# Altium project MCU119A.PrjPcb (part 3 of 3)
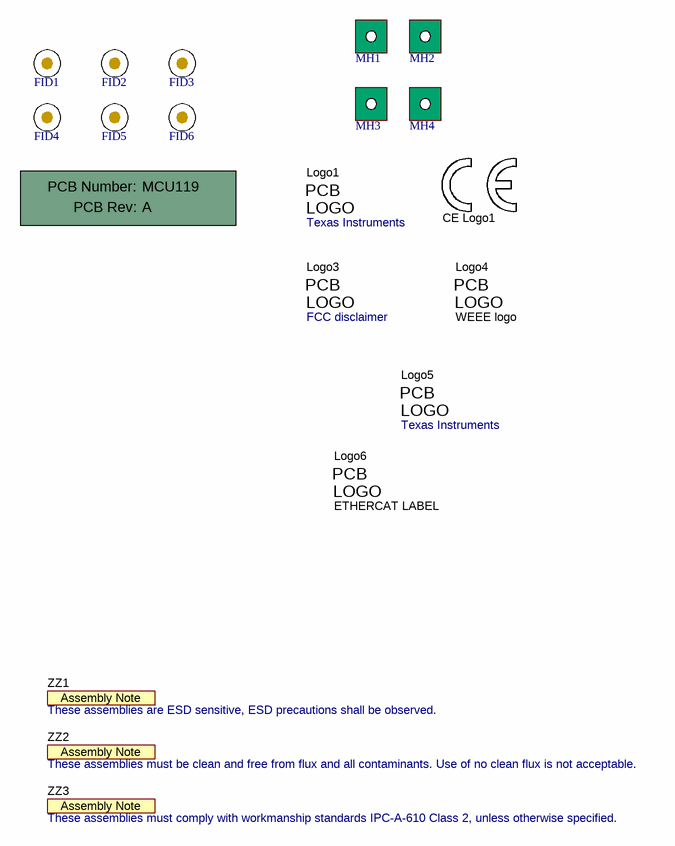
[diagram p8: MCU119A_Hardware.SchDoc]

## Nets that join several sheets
+1V25_MCU: MCU119A_F29H85X_Device (C59.1 L1.1), MCU119A_USB_and_Power (C85.1 L5.2 R72.2 TP11.1)
+3V3_MCU: MCU119A_Connectors (5 pins), MCU119A_F29H85X_Device (6 pins), MCU119A_USB_and_Power (14 pins), MCU119A_XDS110_MCU (R74.2 R76.2), MCU119A_AltRouting_Misc (24 pins)
+3V3_XDS110: MCU119A_USB_and_Power (C126.1 R96.1 U25.5), MCU119A_XDS110_MCU (37 pins)
+5V0_MCU: MCU119A_Connectors (14 pins), MCU119A_USB_and_Power (20 pins), MCU119A_AltRouting_Misc (C22.1 C23.1 U13.23 U13.24)
+5V0_USB: MCU119A_USB_and_Power (12 pins), MCU119A_XDS110_MCU (R164.1)
GND: MCU119A_Connectors (25 pins), MCU119A_F29H85X_Device (38 pins), MCU119A_ADC (34 pins), MCU119A_USB_and_Power (39 pins), MCU119A_XDS110_MCU (13 pins), MCU119A_AltRouting_Misc (36 pins)
USB_GND: MCU119A_USB_and_Power (22 pins), MCU119A_XDS110_MCU (36 pins)
VDD: MCU119A_F29H85X_Device (20 pins), MCU119A_USB_and_Power (C74.2 C75.2 JP4.1 TP1.1)
VDDA: MCU119A_F29H85X_Device (5 pins), MCU119A_ADC (C51.1 C53.1 U3.2 U12.8), MCU119A_USB_and_Power (TP3.1)
VDDIO: MCU119A_F29H85X_Device (30 pins), MCU119A_USB_and_Power (TP2.1)
ADCINA0/DACA_OUT: MCU119A_Connectors (J1/J3.30), MCU119A_ADC (R37.1)
ADCINA1: MCU119A_Connectors (J1/J3.2), MCU119A_ADC (R38.1)
ADCINA2: MCU119A_Connectors (J1/J3.6), MCU119A_ADC (R39.1)
ADCINA3: MCU119A_Connectors (J1/J3.24), MCU119A_ADC (R40.1)
ADCINA4A5_N: MCU119A_Connectors (J10.3), MCU119A_ADC (R42.1)
ADCINA4A5_P: MCU119A_Connectors (J10.1), MCU119A_ADC (R41.1)
ADCINA6: MCU119A_Connectors (J5/J7.64), MCU119A_ADC (R43.1)
ADCINA7: MCU119A_Connectors (J1/J3.28), MCU119A_ADC (R45.1)
ADCINA14/B14/C14/D14/E14: MCU119A_Connectors (J1/J3.23), MCU119A_ADC (R46.1)
ADCINA15/B15/C15/D15/E15: MCU119A_Connectors (J5/J7.63), MCU119A_ADC (R47.1)
ADCINB2B3_N: MCU119A_Connectors (J10.4), MCU119A_ADC (R49.1)
ADCINB2B3_P: MCU119A_Connectors (J10.2), MCU119A_ADC (R48.1)
ADCINB4: MCU119A_Connectors (J1/J3.27), MCU119A_ADC (R50.1)
ADCINB9: MCU119A_Connectors (J5/J7.67), MCU119A_ADC (R51.1)
ADCINC0: MCU119A_Connectors (J5/J7.68), MCU119A_ADC (R52.1)
ADCINC1: MCU119A_Connectors (J1/J3.29), MCU119A_ADC (R53.1)
ADCINC2: MCU119A_Connectors (J5/J7.42), MCU119A_ADC (R54.1)
ADCINC3: MCU119A_Connectors (J5/J7.46), MCU119A_ADC (R55.1)
ADCINC8: MCU119A_Connectors (J5/J7.66), MCU119A_ADC (R56.1)
ADCIND1: MCU119A_Connectors (J1/J3.25), MCU119A_ADC (R57.1)
ADCIND5: MCU119A_Connectors (J5/J7.65), MCU119A_ADC (R58.1)
ADCINE0/DACB_OUT: MCU119A_Connectors (J5/J7.70), MCU119A_ADC (R60.1)
ADCINE1: MCU119A_Connectors (J5/J7.69), MCU119A_ADC (R61.1)
ADCINE7: MCU119A_Connectors (J1/J3.26), MCU119A_ADC (R62.1)
EQEP1A: MCU119A_Connectors (C6.1 J12.1 R5.1), MCU119A_AltRouting_Misc (U13.21)
EQEP1B: MCU119A_Connectors (C7.1 J12.2 R6.1), MCU119A_AltRouting_Misc (U13.20)
EQEP1I: MCU119A_Connectors (C8.1 J12.3 R7.1), MCU119A_AltRouting_Misc (U13.19)
EQEP2A: MCU119A_Connectors (C9.1 J13.1 R8.1), MCU119A_AltRouting_Misc (U13.18)
EQEP2B: MCU119A_Connectors (C10.1 J13.2 R9.1), MCU119A_AltRouting_Misc (U13.17)
EQEP2I: MCU119A_Connectors (C11.1 J13.3 R10.1), MCU119A_AltRouting_Misc (U13.16)
ERRORSTS: MCU119A_F29H85X_Device (U1.74), MCU119A_USB_and_Power (R26.2 R27.2)
GPIO0: MCU119A_Connectors (R1.2), MCU119A_F29H85X_Device (U1.128)
GPIO1: MCU119A_Connectors (R2.2), MCU119A_F29H85X_Device (U1.129)
GPIO2: MCU119A_Connectors (J4/J2.38), MCU119A_F29H85X_Device (U1.130)
GPIO3: MCU119A_Connectors (J4/J2.37), MCU119A_F29H85X_Device (U1.131)
GPIO4: MCU119A_Connectors (J4/J2.36), MCU119A_F29H85X_Device (U1.132)
GPIO5: MCU119A_Connectors (J4/J2.35), MCU119A_F29H85X_Device (U1.133)
GPIO6: MCU119A_Connectors (R3.2), MCU119A_F29H85X_Device (U1.134)
GPIO7: MCU119A_Connectors (R4.2), MCU119A_F29H85X_Device (U1.135)
GPIO8: MCU119A_Connectors (J8/J6.78), MCU119A_F29H85X_Device (U1.138)
GPIO9: MCU119A_Connectors (J8/J6.77), MCU119A_F29H85X_Device (U1.139)
GPIO10: MCU119A_F29H85X_Device (U1.140), MCU119A_AltRouting_Misc (U11.15)
GPIO10_BP: MCU119A_Connectors (J8/J6.57), MCU119A_AltRouting_Misc (U11.1)
GPIO11: MCU119A_F29H85X_Device (U1.141), MCU119A_AltRouting_Misc (U11.14)
GPIO11_BP: MCU119A_Connectors (J8/J6.58), MCU119A_AltRouting_Misc (U11.13)
GPIO12: MCU119A_Connectors (J8/J6.76), MCU119A_F29H85X_Device (U1.142)
GPIO13: MCU119A_Connectors (J8/J6.75), MCU119A_F29H85X_Device (U1.143)
GPIO14: MCU119A_Connectors (J4/J2.34), MCU119A_F29H85X_Device (U1.144)
GPIO15: MCU119A_Connectors (J4/J2.33), MCU119A_F29H85X_Device (U1.1)
GPIO17: MCU119A_F29H85X_Device (U1.4), MCU119A_AltRouting_Misc (U14.15)
GPIO17_BP: MCU119A_Connectors (J4/J2.17), MCU119A_AltRouting_Misc (U14.1)
GPIO18: MCU119A_Connectors (J4/J2.11), MCU119A_F29H85X_Device (U1.10)
GPIO19: MCU119A_Connectors (J4/J2.13), MCU119A_F29H85X_Device (U1.5), MCU119A_AltRouting_Misc (R17.1)
GPIO22: MCU119A_Connectors (J5/J7.50), MCU119A_F29H85X_Device (U1.11), MCU119A_USB_and_Power (R32.1)
GPIO23: MCU119A_Connectors (J15.5 R24.2), MCU119A_F29H85X_Device (U1.127)
GPIO24: MCU119A_Connectors (J8/J6.74), MCU119A_F29H85X_Device (U1.126)
GPIO25: MCU119A_Connectors (J8/J6.54), MCU119A_F29H85X_Device (U1.125)
GPIO26: MCU119A_Connectors (J5/J7.47), MCU119A_F29H85X_Device (U1.124)
GPIO29: MCU119A_Connectors (J15.2 R23.1), MCU119A_F29H85X_Device (U1.121)
GPIO30: MCU119A_F29H85X_Device (U1.120), MCU119A_USB_and_Power (U10.21)
GPIO32: MCU119A_F29H85X_Device (U1.96), MCU119A_AltRouting_Misc (U11.4)
GPIO32_BP: MCU119A_Connectors (J8/J6.52), MCU119A_AltRouting_Misc (U11.3)
GPIO34: MCU119A_F29H85X_Device (U1.7), MCU119A_AltRouting_Misc (U14.4)
GPIO34_BP: MCU119A_Connectors (J4/J2.12), MCU119A_AltRouting_Misc (U14.3)
GPIO38: MCU119A_Connectors (J5/J7.45), MCU119A_F29H85X_Device (U1.104)
GPIO41: MCU119A_Connectors (J5/J7.49), MCU119A_F29H85X_Device (U1.73), MCU119A_USB_and_Power (R29.1)
GPIO42: MCU119A_F29H85X_Device (U1.107), MCU119A_AltRouting_Misc (U6.6)
GPIO42_BP: MCU119A_Connectors (J1/J3.4), MCU119A_AltRouting_Misc (U6.4)
GPIO43: MCU119A_F29H85X_Device (U1.108), MCU119A_AltRouting_Misc (U6.10)
GPIO43_BP: MCU119A_Connectors (J1/J3.3), MCU119A_AltRouting_Misc (U6.2)
GPIO49_FSITXD0: MCU119A_Connectors (J11.6), MCU119A_F29H85X_Device (U1.75)
GPIO50_FSITXD1: MCU119A_Connectors (J11.8), MCU119A_F29H85X_Device (U1.76)
GPIO51_FSITXCLK: MCU119A_Connectors (J11.2), MCU119A_F29H85X_Device (U1.77)
GPIO52_FSIRXD0: MCU119A_Connectors (J11.5), MCU119A_F29H85X_Device (U1.78)
GPIO53_FSIRXD1: MCU119A_Connectors (J11.7), MCU119A_F29H85X_Device (U1.79)
GPIO54_FSIRXCLK: MCU119A_Connectors (J11.1), MCU119A_F29H85X_Device (U1.80)
GPIO56: MCU119A_Connectors (J1/J3.10), MCU119A_F29H85X_Device (U1.82)
GPIO57: MCU119A_Connectors (J1/J3.9), MCU119A_F29H85X_Device (U1.84)
GPIO58: MCU119A_Connectors (J4/J2.15), MCU119A_F29H85X_Device (U1.85)
GPIO59: MCU119A_Connectors (J4/J2.14), MCU119A_F29H85X_Device (U1.86)
GPIO60: MCU119A_Connectors (J1/J3.7), MCU119A_F29H85X_Device (U1.88)
GPIO61: MCU119A_Connectors (J4/J2.19), MCU119A_F29H85X_Device (U1.89)
GPIO62: MCU119A_Connectors (J8/J6.53), MCU119A_F29H85X_Device (U1.90), MCU119A_AltRouting_Misc (R19.1)
GPIO63: MCU119A_Connectors (J8/J6.55), MCU119A_F29H85X_Device (U1.91)
GPIO64: MCU119A_F29H85X_Device (U1.92), MCU119A_AltRouting_Misc (S4.2)
GPIO64_BP: MCU119A_Connectors (J4/J2.32), MCU119A_AltRouting_Misc (S4.3)
GPIO64_CANTX: MCU119A_Connectors (TP7.1 U15.1), MCU119A_AltRouting_Misc (S4.1)
GPIO65: MCU119A_F29H85X_Device (U1.93), MCU119A_AltRouting_Misc (S4.5)
GPIO65_BP: MCU119A_Connectors (J4/J2.31), MCU119A_AltRouting_Misc (S4.6)
GPIO65_CANRX: MCU119A_Connectors (TP8.1 U15.4), MCU119A_AltRouting_Misc (S4.4)
GPIO66: MCU119A_Connectors (J8/J6.59), MCU119A_F29H85X_Device (U1.94)
GPIO68: MCU119A_Connectors (J8/J6.73), MCU119A_F29H85X_Device (U1.109)
GPIO70: MCU119A_F29H85X_Device (U1.110), MCU119A_AltRouting_Misc (U8.10)
GPIO70_BP: MCU119A_Connectors (J5/J7.44), MCU119A_AltRouting_Misc (U8.9)
GPIO71: MCU119A_F29H85X_Device (U1.111), MCU119A_AltRouting_Misc (U8.6)
GPIO71_BP: MCU119A_Connectors (J5/J7.43), MCU119A_AltRouting_Misc (U8.7)
GPIO72: MCU119A_Connectors (J1/J3.8), MCU119A_F29H85X_Device (U1.114), MCU119A_AltRouting_Misc (R31.1)
GPIO76: MCU119A_Connectors (J8/J6.72), MCU119A_F29H85X_Device (U1.115)
GPIO77: MCU119A_Connectors (J8/J6.71), MCU119A_F29H85X_Device (U1.116)
GPIO78: MCU119A_Connectors (J1/J3.5), MCU119A_F29H85X_Device (U1.117)
GPIO84: MCU119A_F29H85X_Device (U1.119), MCU119A_AltRouting_Misc (R33.2 U14.14)
GPIO84_BP: MCU119A_Connectors (J4/J2.18), MCU119A_AltRouting_Misc (U14.13)
GPIO103: MCU119A_Connectors (J5/J7.48), MCU119A_F29H85X_Device (U1.105)
GPIO127: MCU119A_Connectors (J8/J6.51), MCU119A_F29H85X_Device (U1.97)
GPIO220_X1: MCU119A_F29H85X_Device (U1.102), MCU119A_AltRouting_Misc (R21.1)
GPIO221_X2: MCU119A_F29H85X_Device (U1.100), MCU119A_AltRouting_Misc (R20.1)
MCU_RXD: MCU119A_XDS110_MCU (R165.1), MCU119A_AltRouting_Misc (U9.6)
MCU_TCK: MCU119A_F29H85X_Device (U1.70), MCU119A_XDS110_MCU (R98.1)
MCU_TDI: MCU119A_F29H85X_Device (U1.64), MCU119A_XDS110_MCU (R99.1)
MCU_TDO: MCU119A_F29H85X_Device (U1.65), MCU119A_XDS110_MCU (R100.1)
MCU_TMS: MCU119A_F29H85X_Device (R44.1 U1.69), MCU119A_XDS110_MCU (R97.1)
MCU_TXD: MCU119A_XDS110_MCU (R171.1), MCU119A_AltRouting_Misc (U9.10)
USB_D_N: MCU119A_USB_and_Power (U16.1 U16.10 USB1.A7 USB1.B7), MCU119A_XDS110_MCU (U2.93)
USB_D_P: MCU119A_USB_and_Power (U16.2 U16.9 USB1.A6 USB1.B6), MCU119A_XDS110_MCU (U2.94)
XRSn: MCU119A_Connectors (J4/J2.16 J8/J6.56), MCU119A_F29H85X_Device (C28.1 R59.1 S1.4 U1.103), MCU119A_USB_and_Power (U10.6)

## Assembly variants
001: not fitted C1 C2 C3 C4 C24 C25 C26 C27 C29 C30 C31 C32 C33 C34 C35 C36 C37 C38 C39 C40 C41 C42 C43 C44 C45 C46 C47 C48 C49 C50 C80 FID1 FID2 FID3 FID4 FID5 FID6 R26 R27 R29 R30 R32 R34 R68 R175
002: not fitted C1 C2 C3 C4 C24 C25 C26 C27 C29 C30 C31 C32 C33 C34 C35 C36 C37 C38 C39 C40 C41 C42 C43 C44 C45 C46 C47 C48 C49 C50 C80 FID1 FID2 FID3 FID4 FID5 FID6 R18 R30 R34 R68 R175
